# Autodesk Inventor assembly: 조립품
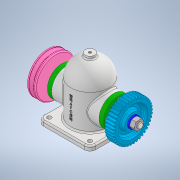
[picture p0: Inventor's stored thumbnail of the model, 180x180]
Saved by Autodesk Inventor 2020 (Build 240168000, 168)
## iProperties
Created: 2021-07
Part Number: 조립품
Document SubType Name: Assembly
Designer: Owner
Author: Owner
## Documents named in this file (14)
- C:\Users\Owner\Desktop\710716V1004\조립품.iam
- C:\Users\Owner\Desktop\710716V1004\본체.ipt
- C:\Users\Owner\Desktop\710716V1004\V-벨트풀리.ipt
- V-벨트풀리.ipt
- C:\Users\Owner\Desktop\710716V1004\너트 M12x1.25.ipt
- C:\Users\Owner\Desktop\710716V1004\베어링 6203.ipt
- C:\Users\Owner\Desktop\710716V1004\볼트 M4.ipt
- C:\Users\Owner\Desktop\710716V1004\부시.ipt
- C:\Users\Owner\Desktop\710716V1004\스퍼기어.ipt
- C:\Users\Owner\Desktop\710716V1004\오일 실 26 38 8.ipt
- C:\Users\Owner\Desktop\710716V1004\와셔 12x24.ipt
- C:\Users\Owner\Desktop\710716V1004\축.ipt
- C:\Users\Owner\Desktop\710716V1004\커버.ipt
- C:\Users\Owner\Desktop\710716V1004\키 5x5x12.ipt
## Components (1 placed, 1 different names)
1. V-벨트풀리:1
